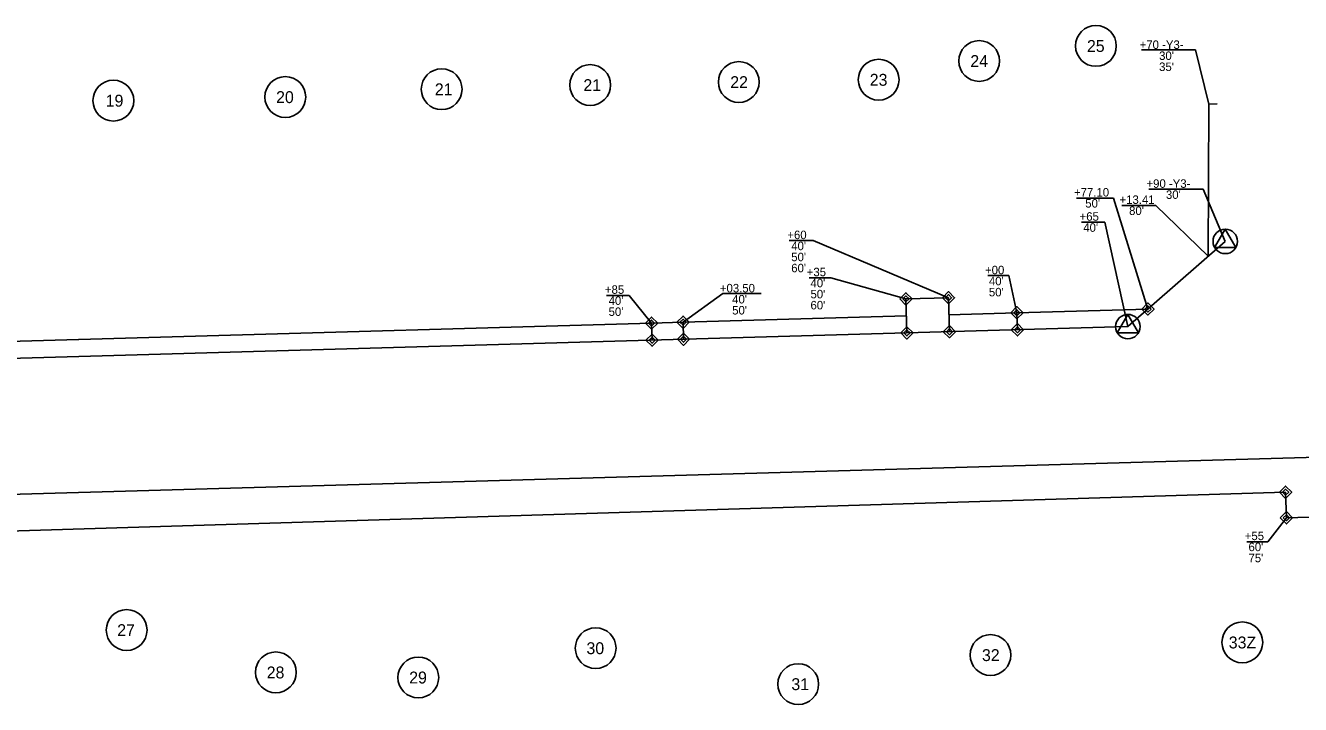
# Model space of a CAD drawing. Extents: x 1756120 to 1760612, y 736784 to 737319.
# Drawn here: x 1758199 to 1758949, y 736833 to 737233 of the extents above; entities that cross this region are included whole.
import ezdxf

# ---------------------------------------------------------------- set-up
doc = ezdxf.new("R2010")
doc.units = 0
for name, color, linetype in [('Prop Easement Construction', 7, 'Continuous'), ('Prop Easement Construction Station Offsets', 7, 'Continuous'), ('Prop Easement Permanent Drainage', 7, 'Continuous'), ('Prop Easement Permanent Drainage Station Offsets', 7, 'Continuous'), ('Prop Easement Permanent Utility', 7, 'Continuous'), ('Prop Easement Permanent Utility Station Offsets', 7, 'Continuous'), ('Prop Parcel Number CELL', 7, 'Continuous'), ('Prop Parcel Number Text', 7, 'Continuous'), ('Prop ROW Marker CELL', 7, 'Continuous'), ('Prop ROW Permanent Easement CELL', 7, 'Continuous'), ('Prop ROW RW Lines', 7, 'Continuous'), ('Prop ROW Station Offsets', 7, 'Continuous')]:
    doc.layers.add(name, color=color, linetype=linetype)

msp = doc.modelspace()

# ---------------------------------------------------------------- linework, layer by layer
at = {"layer": 'Prop Easement Construction'}
for p, q in [((1758894.39, 737096.96), (1758894.76, 737186.37)), ((1758894.76, 737186.37), (1758899.75, 737186.58)), ((1758585.45, 737058.18), (1758716.9, 737061.91)), ((1758741.89, 737062.62), (1758781.87, 737063.76)), ((1758077.16, 737043.75), (1758566.96, 737057.65))]:
    msp.add_line(p, q, dxfattribs=at)
at = {"layer": 'Prop Easement Construction Station Offsets'}
for p, q in [((1758886.99, 737218.35), (1758855.13, 737218.35)), ((1758894.76, 737186.37), (1758886.99, 737218.35)), ((1758863.64, 737126.94), (1758843.64, 737126.94)), ((1758894.39, 737096.96), (1758863.64, 737126.94))]:
    msp.add_line(p, q, dxfattribs=at)
at = {"layer": 'Prop Easement Permanent Drainage'}
for q in [(1758858.94, 737065.95), (1758782.16, 737053.76)]:
    msp.add_line((1758781.87, 737063.76), q, dxfattribs=at)
at = {"layer": 'Prop Easement Permanent Drainage Station Offsets'}
for p, q in [((1758816.82, 737131.24), (1758838.6, 737131.24)), ((1758858.94, 737065.95), (1758838.6, 737131.24)), ((1758764.74, 737085.72), (1758777.12, 737085.72)), ((1758777.12, 737085.72), (1758781.87, 737063.76))]:
    msp.add_line(p, q, dxfattribs=at)
at = {"layer": 'Prop Easement Permanent Utility'}
for p, q in [((1758716.62, 737071.91), (1758741.61, 737072.62)), ((1758717.18, 737051.92), (1758716.62, 737071.91)), ((1758742.17, 737052.63), (1758741.61, 737072.62)), ((1758566.96, 737057.65), (1758585.45, 737058.18)), ((1758585.45, 737058.18), (1758585.74, 737048.18)), ((1758566.96, 737057.65), (1758567.25, 737047.66)), ((1757995.37, 736929.38), (1758939.93, 736958.2)), ((1758939.93, 736958.2), (1758940.36, 736943.21)), ((1758940.36, 736943.21), (1758960.35, 736943.77))]:
    msp.add_line(p, q, dxfattribs=at)
at = {"layer": 'Prop Easement Permanent Utility Station Offsets'}
for p, q in [((1758647.9, 737106.22), (1758662.03, 737106.22)), ((1758741.61, 737072.62), (1758662.03, 737106.22)), ((1758659.6, 737084.31), (1758672.38, 737084.31)), ((1758716.62, 737071.91), (1758672.38, 737084.31)), ((1758540.51, 737073.97), (1758553.8, 737073.97)), ((1758566.96, 737057.65), (1758553.8, 737073.97)), ((1758585.45, 737058.18), (1758608.79, 737075.04)), ((1758608.79, 737075.04), (1758631.52, 737075.04)), ((1758929.56, 736929.02), (1758940.36, 736943.21)), ((1758917.05, 736929.02), (1758929.56, 736929.02))]:
    msp.add_line(p, q, dxfattribs=at)
at = {"layer": 'Prop Parcel Number CELL'}
for centre in [(1758828.34, 737220.71), (1758759.68, 737211.84), (1758530.87, 737197.7), (1758618.26, 737199.46), (1758700.55, 737200.83), (1758351.5, 737190.64), (1758443.48, 737195.23), (1758250.37, 737188.53), (1758258.19, 736877.14), (1758534.08, 736866.51), (1758914.47, 736869.9), (1758766.32, 736862.45), (1758345.97, 736852.26), (1758429.73, 736849.27), (1758653.23, 736845.36)]:
    msp.add_circle(centre, 12, dxfattribs=at)
at = {"layer": 'Prop ROW Marker CELL'}
for p, q in [((1758904.42, 737105.74), (1758904.42, 737105.74)), ((1758716.62, 737071.91), (1758716.62, 737071.91)), ((1758741.61, 737072.62), (1758741.61, 737072.62)), ((1758858.94, 737065.95), (1758858.94, 737065.95)), ((1758585.45, 737058.18), (1758585.45, 737058.18)), ((1758781.87, 737063.76), (1758781.87, 737063.76)), ((1758566.96, 737057.65), (1758566.96, 737057.65)), ((1758717.18, 737051.92), (1758717.18, 737051.92)), ((1758742.17, 737052.63), (1758742.17, 737052.63)), ((1758782.16, 737053.76), (1758782.16, 737053.76)), ((1758847.13, 737055.61), (1758847.13, 737055.61)), ((1758567.25, 737047.66), (1758567.25, 737047.66)), ((1758585.74, 737048.18), (1758585.74, 737048.18)), ((1758939.93, 736958.2), (1758939.93, 736958.2)), ((1758940.36, 736943.21), (1758940.36, 736943.21))]:
    msp.add_line(p, q, dxfattribs=at)
for points in [[(1758898.17, 737102.14), (1758904.42, 737112.94), (1758910.67, 737102.14)], [(1758840.88, 737052.01), (1758847.13, 737062.81), (1758853.38, 737052.01)]]:
    msp.add_lwpolyline(points, close=True, dxfattribs=at)
for centre in [(1758904.42, 737105.74), (1758847.13, 737055.61)]:
    msp.add_circle(centre, 7.2, dxfattribs=at)
at = {"layer": 'Prop ROW Permanent Easement CELL'}
for points in [[(1758713.02, 737071.91), (1758716.62, 737075.51), (1758720.22, 737071.91), (1758716.62, 737068.31)], [(1758714.82, 737071.91), (1758716.62, 737073.71), (1758718.42, 737071.91), (1758716.62, 737070.11)], [(1758738.01, 737072.62), (1758741.61, 737076.22), (1758745.21, 737072.62), (1758741.61, 737069.02)], [(1758739.81, 737072.62), (1758741.61, 737074.42), (1758743.41, 737072.62), (1758741.61, 737070.82)], [(1758778.28, 737063.76), (1758781.88, 737067.36), (1758785.47, 737063.76), (1758781.88, 737060.16)], [(1758855.34, 737065.95), (1758858.94, 737069.55), (1758862.54, 737065.95), (1758858.94, 737062.35)], [(1758857.14, 737065.95), (1758858.94, 737067.75), (1758860.74, 737065.95), (1758858.94, 737064.15)], [(1758563.36, 737057.65), (1758566.96, 737061.25), (1758570.56, 737057.65), (1758566.96, 737054.05)], [(1758565.16, 737057.65), (1758566.96, 737059.45), (1758568.76, 737057.65), (1758566.96, 737055.85)], [(1758581.85, 737058.18), (1758585.45, 737061.78), (1758589.05, 737058.18), (1758585.45, 737054.58)], [(1758583.65, 737058.18), (1758585.45, 737059.98), (1758587.25, 737058.18), (1758585.45, 737056.38)], [(1758780.07, 737063.76), (1758781.87, 737065.56), (1758783.67, 737063.76), (1758781.87, 737061.96)], [(1758563.65, 737047.66), (1758567.25, 737051.26), (1758570.84, 737047.66), (1758567.25, 737044.06)], [(1758582.14, 737048.18), (1758585.74, 737051.78), (1758589.34, 737048.18), (1758585.74, 737044.58)], [(1758713.59, 737051.92), (1758717.19, 737055.52), (1758720.78, 737051.92), (1758717.19, 737048.32)], [(1758715.38, 737051.92), (1758717.18, 737053.72), (1758718.98, 737051.92), (1758717.18, 737050.12)], [(1758738.58, 737052.63), (1758742.18, 737056.23), (1758745.77, 737052.63), (1758742.18, 737049.03)], [(1758740.37, 737052.63), (1758742.17, 737054.43), (1758743.97, 737052.63), (1758742.17, 737050.83)], [(1758778.56, 737053.76), (1758782.16, 737057.36), (1758785.76, 737053.76), (1758782.16, 737050.16)], [(1758780.36, 737053.76), (1758782.16, 737055.56), (1758783.96, 737053.76), (1758782.16, 737051.96)], [(1758565.45, 737047.66), (1758567.25, 737049.46), (1758569.04, 737047.66), (1758567.25, 737045.86)], [(1758583.94, 737048.18), (1758585.74, 737049.98), (1758587.54, 737048.18), (1758585.74, 737046.38)], [(1758936.33, 736958.2), (1758939.93, 736961.8), (1758943.53, 736958.2), (1758939.93, 736954.6)], [(1758938.13, 736958.2), (1758939.93, 736960), (1758941.73, 736958.2), (1758939.93, 736956.4)], [(1758936.76, 736943.21), (1758940.36, 736946.81), (1758943.96, 736943.21), (1758940.36, 736939.61)], [(1758938.56, 736943.21), (1758940.36, 736945.01), (1758942.16, 736943.21), (1758940.36, 736941.41)]]:
    msp.add_lwpolyline(points, close=True, dxfattribs=at)
at = {"layer": 'Prop ROW RW Lines'}
for p, q in [((1758847.13, 737055.61), (1758904.42, 737105.74)), ((1758082.44, 737033.89), (1758847.13, 737055.61)), ((1758084.71, 736953.92), (1759384.18, 736990.82))]:
    msp.add_line(p, q, dxfattribs=at)
at = {"layer": 'Prop ROW Station Offsets'}
for p, q in [((1758891.36, 737136.49), (1758859.46, 737136.49)), ((1758833.52, 737117.14), (1758819.81, 737117.14))]:
    msp.add_line(p, q, dxfattribs=at)
for points in [[(1758891.36, 737136.49), (1758904.42, 737105.74)], [(1758833.52, 737117.14), (1758847.13, 737055.61)]]:
    msp.add_lwpolyline(points, dxfattribs=at)

# ---------------------------------------------------------------- texts
at = {"layer": 'Prop Easement Construction Station Offsets'}
for s, p in [('+70 -Y3-', (1758854.06, 737218.95)), ("30'", (1758865.51, 737212.45)), ("35'", (1758865.51, 737205.95)), ('+13.41', (1758842.21, 737127.78)), ("80'", (1758847.85, 737121.28))]:
    msp.add_text(s, height=5, dxfattribs=at).set_placement(p)
at = {"layer": 'Prop Easement Permanent Drainage Station Offsets'}
for s, p in [('+77.10', (1758815.44, 737132.12)), ("50'", (1758822.07, 737125.62)), ('+00', (1758763.11, 737086.41)), ("40'", (1758765.39, 737079.91)), ("50'", (1758765.39, 737073.41))]:
    msp.add_text(s, height=5, rotation=0.00001, dxfattribs=at).set_placement(p)
at = {"layer": 'Prop Easement Permanent Utility Station Offsets'}
for s, p in [('+60', (1758646.83, 737107.07)), ("40'", (1758649.12, 737100.57)), ("50'", (1758649.12, 737094.07)), ("60'", (1758649.12, 737087.57)), ('+35', (1758658.24, 737085.24)), ('+03.50', (1758607.14, 737075.73)), ("40'", (1758660.43, 737078.74)), ('+85', (1758539.51, 737074.9)), ("40'", (1758541.69, 737068.4)), ("40'", (1758614.37, 737069.23)), ("50'", (1758660.43, 737072.24)), ("50'", (1758541.69, 737061.9)), ("50'", (1758614.37, 737062.73)), ("60'", (1758660.43, 737065.74)), ('+55', (1758915.9, 736930.04)), ("60'", (1758918.08, 736923.54)), ("75'", (1758918.08, 736917.04))]:
    msp.add_text(s, height=5, rotation=0.00001, dxfattribs=at).set_placement(p)
at = {"layer": 'Prop Parcel Number Text'}
for s, p in [('25', (1758823.06, 737217.16)), ('24', (1758754.46, 737208.29)), ('21', (1758526.84, 737194.14)), ('22', (1758613.23, 737195.9)), ('23', (1758695.29, 737197.28)), ('20', (1758346.09, 737187.09)), ('21', (1758439.45, 737191.67)), ('19', (1758245.85, 737184.98)), ('27', (1758252.62, 736873.58)), ('33Z', (1758906.47, 736866.34)), ('30', (1758528.66, 736862.96)), ('32', (1758761.29, 736858.9)), ('28', (1758340.57, 736848.7)), ('29', (1758424.38, 736845.72)), ('31', (1758649.2, 736841.81))]:
    msp.add_text(s, height=7, rotation=0.00001, dxfattribs=at).set_placement(p)
at = {"layer": 'Prop ROW Station Offsets'}
for s, p in [('+90 -Y3-', (1758858.08, 737137.24)), ("30'", (1758869.53, 737130.74)), ('+65', (1758818.73, 737117.89)), ("40'", (1758820.91, 737111.39))]:
    msp.add_text(s, height=5, dxfattribs=at).set_placement(p)

doc.saveas('drawing.dxf')
